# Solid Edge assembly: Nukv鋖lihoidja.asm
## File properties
Author: Türk
Template: Iso Assembly.asm
Last saved by: Türk
Revision: 2
Application: Solid Edge
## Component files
lli hoidja.par
llipolt.par
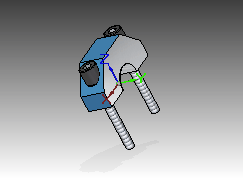
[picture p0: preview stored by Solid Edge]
